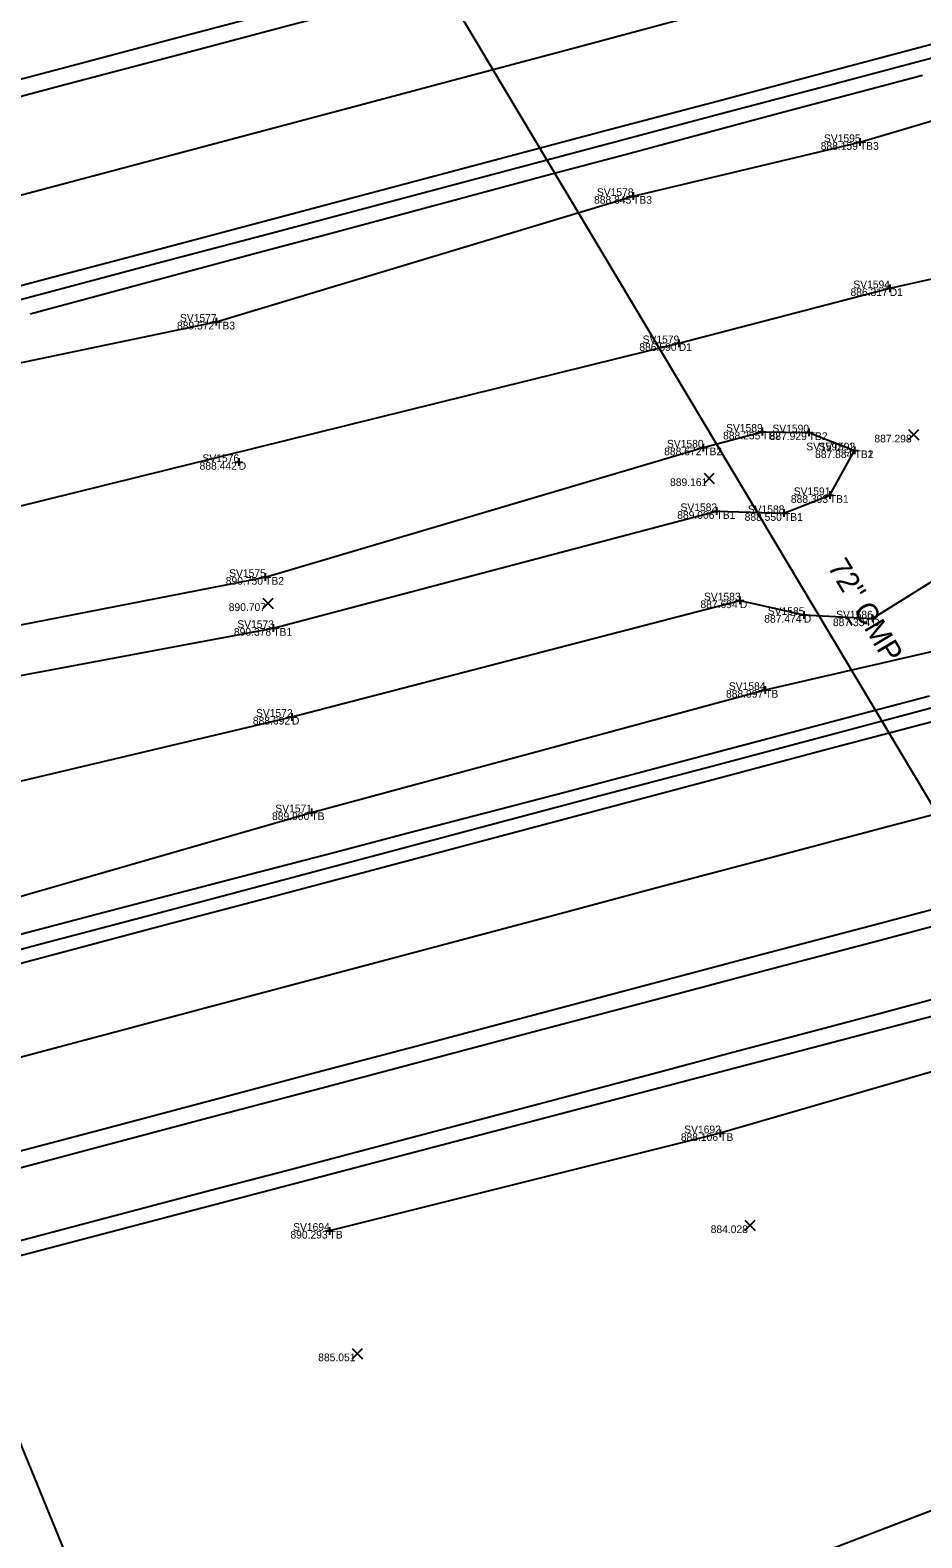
# Model space of a CAD drawing. Extents: x 2125299 to 2129212, y 713100 to 714300.
# Drawn here: x 2127549.2 to 2127665, y 713703.4 to 713899.3 of the extents above; entities that cross this region are included whole.
import ezdxf

# ---------------------------------------------------------------- set-up
doc = ezdxf.new("R2010")
doc.units = 0
for name, color, linetype in [('_CIVIL_CONSTRUCTION', 7, 'Continuous'), ('DR_X_Ditch', 7, 'Continuous'), ('DR_X_Storm_Sewer', 7, 'Continuous'), ('DR_X_Text', 7, 'Continuous'), ('DT_X_Terrain_Boundary', 7, 'Continuous'), ('PV_X_EOP', 7, 'Continuous'), ('PV_X_Shoulder_Rumble_Strip', 7, 'Continuous'), ('RW_P_Esmt_TMP', 7, 'Continuous'), ('RW_X_Esmt_CH', 7, 'Continuous'), ('RW_X_Fee_WL', 7, 'Continuous'), ('SC_Scratch1', 7, 'Continuous'), ('SC_Scratch2', 7, 'Continuous'), ('SV_X_Mon_Cells_Found', 7, 'Continuous'), ('SV_X_Text_Elevation', 7, 'Continuous'), ('SV_X_Toe_of_Slope', 7, 'Continuous'), ('SV_X_Top_of_Bank', 7, 'Continuous')]:
    doc.layers.add(name, color=color, linetype=linetype)

msp = doc.modelspace()

# ---------------------------------------------------------------- linework, layer by layer
at = {"layer": '_CIVIL_CONSTRUCTION'}
for points in [[(2127372.97, 713831.37), (2127387.47, 713835.22), (2127401.97, 713839.08), (2127416.46, 713842.93), (2127430.96, 713846.79), (2127445.46, 713850.64), (2127459.95, 713854.5), (2127474.45, 713858.35), (2127488.94, 713862.21), (2127503.44, 713866.06), (2127517.94, 713869.92), (2127532.43, 713873.77), (2127546.93, 713877.63), (2127561.42, 713881.48), (2127575.92, 713885.34), (2127590.42, 713889.19), (2127604.91, 713893.05), (2127619.41, 713896.9), (2127633.91, 713900.76), (2127648.4, 713904.61), (2127662.9, 713908.47), (2127677.41, 713912.28)], [(2127369.79, 713718.59), (2127384.29, 713722.43), (2127398.79, 713726.27), (2127413.29, 713730.11), (2127427.79, 713733.95), (2127442.29, 713737.79), (2127456.79, 713741.63), (2127471.29, 713745.47), (2127485.79, 713749.32), (2127500.28, 713753.18), (2127514.78, 713757.04), (2127529.27, 713760.9), (2127543.77, 713764.76), (2127558.26, 713768.62), (2127572.75, 713772.48), (2127587.25, 713776.34), (2127601.74, 713780.2), (2127616.24, 713784.07), (2127630.73, 713787.93), (2127645.23, 713791.77), (2127659.73, 713795.61), (2127674.23, 713799.44)]]:
    msp.add_lwpolyline(points, dxfattribs=at)
at = {"layer": 'DR_X_Ditch'}
for points in [[(2127104.46, 713722.2), (2127161.17, 713739.36), (2127224.94, 713755.07), (2127279.95, 713770.84), (2127341.71, 713787.57), (2127396.23, 713800.84), (2127459.54, 713814.71), (2127515.88, 713829.56), (2127633.42, 713858.63), (2127660.82, 713865.77), (2127680.17, 713870.09), (2127707.74, 713876.68), (2127734.62, 713883.6), (2127780.13, 713896.01), (2127811.25, 713900.24), (2127854.87, 713906.28), (2127890.1, 713912.55), (2127900.96, 713914.65)], [(2127114.72, 713683.53), (2127174.42, 713700.51), (2127233.48, 713715.29), (2127290.34, 713734.33), (2127349.42, 713751.95), (2127405.14, 713769), (2127465.12, 713782.63), (2127526.43, 713796.66), (2127583.18, 713810.08), (2127641.36, 713825.21), (2127649.66, 713823.32), (2127658.57, 713822.87), (2127670.43, 713830.25), (2127710.74, 713841.25), (2127737.15, 713847.1), (2127758.83, 713851.78)]]:
    msp.add_lwpolyline(points, dxfattribs=at)
at = {"layer": 'DR_X_Storm_Sewer'}
msp.add_line((2127551.46, 713991.15), (2127754.53, 713650.69), dxfattribs=at)
at = {"layer": 'DR_X_Text'}
msp.add_line((2127655.93, 713821.99), (2127655.44, 713822.83), dxfattribs=at)
at = {"layer": 'DT_X_Terrain_Boundary'}
msp.add_lwpolyline([(2127379.41, 713697.54), (2127389.08, 713700.09), (2127398.75, 713702.64), (2127408.42, 713705.18), (2127418.09, 713707.74), (2127427.76, 713710.3), (2127437.42, 713712.86), (2127447.09, 713715.42), (2127456.76, 713717.99), (2127466.42, 713720.55), (2127476.09, 713723.11), (2127485.74, 713725.66), (2127495.42, 713728.23), (2127505.09, 713730.78), (2127514.76, 713733.32), (2127524.43, 713735.87), (2127546.22, 713719.73), (2127560.16, 713685.63), (2127560.57, 713676.96), (2127582.81, 713665.2), (2127597.81, 713640.57), (2127738.64, 713599.23)], dxfattribs=at)
at = {"layer": 'PV_X_EOP'}
for points in [[(2127549.17, 713862.45), (2127558.82, 713865.04), (2127568.48, 713867.64), (2127578.14, 713870.23), (2127587.8, 713872.82), (2127597.46, 713875.41), (2127607.12, 713877.99), (2127616.78, 713880.58), (2127626.44, 713883.16), (2127636.1, 713885.74), (2127645.76, 713888.33), (2127655.42, 713890.89), (2127665.1, 713893.44)], [(2127540.23, 713779.85), (2127549.91, 713782.38), (2127559.59, 713784.9), (2127569.26, 713787.42), (2127578.94, 713789.95), (2127588.61, 713792.47), (2127598.29, 713794.99), (2127607.97, 713797.52), (2127617.64, 713800.04), (2127627.32, 713802.57), (2127636.98, 713805.13), (2127646.65, 713807.7), (2127656.31, 713810.27), (2127665.98, 713812.83)], [(2127543.78, 713740.96), (2127553.45, 713743.5), (2127563.12, 713746.05), (2127572.79, 713748.6), (2127582.46, 713751.14), (2127592.13, 713753.69), (2127601.8, 713756.23), (2127611.47, 713758.78), (2127621.14, 713761.34), (2127630.8, 713763.91), (2127640.46, 713766.49), (2127650.13, 713769.06), (2127659.79, 713771.64), (2127669.45, 713774.21)]]:
    msp.add_lwpolyline(points, dxfattribs=at)
at = {"layer": 'PV_X_Shoulder_Rumble_Strip'}
for points in [[(2127379.28, 713847.95), (2127393.77, 713851.83), (2127408.26, 713855.7), (2127422.75, 713859.58), (2127437.24, 713863.45), (2127451.73, 713867.33), (2127466.21, 713871.2), (2127480.7, 713875.08), (2127495.19, 713878.95), (2127509.68, 713882.82), (2127524.17, 713886.66), (2127538.67, 713890.5), (2127553.17, 713894.33), (2127567.67, 713898.17), (2127582.17, 713902), (2127596.67, 713905.84), (2127611.16, 713909.67), (2127625.66, 713913.5), (2127640.16, 713917.34), (2127654.66, 713921.17), (2127669.16, 713925.01)], [(2127378.03, 713819.22), (2127392.53, 713823.07), (2127407.02, 713826.92), (2127421.52, 713830.76), (2127436.02, 713834.61), (2127450.51, 713838.46), (2127465.01, 713842.3), (2127479.5, 713846.15), (2127494, 713849.99), (2127508.49, 713853.84), (2127522.99, 713857.69), (2127537.48, 713861.53), (2127551.98, 713865.38), (2127566.47, 713869.23), (2127580.97, 713873.07), (2127595.46, 713876.92), (2127609.96, 713880.76), (2127624.46, 713884.61), (2127638.95, 713888.46), (2127653.45, 713892.3), (2127667.94, 713896.15)], [(2127376.81, 713734.43), (2127391.3, 713738.29), (2127405.79, 713742.13), (2127420.29, 713745.98), (2127434.79, 713749.83), (2127449.28, 713753.68), (2127463.77, 713757.52), (2127478.27, 713761.37), (2127492.76, 713765.22), (2127507.26, 713769.07), (2127521.75, 713772.91), (2127536.25, 713776.76), (2127550.74, 713780.61), (2127565.24, 713784.46), (2127579.73, 713788.3), (2127594.23, 713792.15), (2127608.72, 713796), (2127623.22, 713799.85), (2127637.71, 713803.69), (2127652.21, 713807.54), (2127666.7, 713811.39)], [(2127369.47, 713704.27), (2127383.96, 713708.1), (2127398.46, 713711.94), (2127412.96, 713715.77), (2127427.46, 713719.61), (2127441.96, 713723.44), (2127456.45, 713727.28), (2127470.95, 713731.12), (2127485.45, 713734.96), (2127499.95, 713738.8), (2127514.44, 713742.64), (2127528.94, 713746.48), (2127543.43, 713750.32), (2127557.93, 713754.16), (2127572.43, 713758), (2127586.92, 713761.84), (2127601.42, 713765.68), (2127615.92, 713769.52), (2127630.41, 713773.36), (2127644.91, 713777.2), (2127659.41, 713781.04), (2127673.9, 713784.89)]]:
    msp.add_lwpolyline(points, dxfattribs=at)
at = {"layer": 'SC_Scratch1'}
msp.add_lwpolyline([(2127133.38, 713627.43), (2127166.26, 713637.18), (2127280.77, 713668.85), (2127395.3, 713699.47), (2127509.42, 713729.99), (2127750.89, 713793.4), (2127929.41, 713841.22)], dxfattribs=at)
at = {"layer": 'SC_Scratch2'}
for points in [[(2127379.92, 713845.89), (2127394.41, 713849.77), (2127408.9, 713853.64), (2127423.39, 713857.52), (2127437.89, 713861.39), (2127452.38, 713865.27), (2127466.87, 713869.14), (2127481.36, 713873.02), (2127495.85, 713876.89), (2127510.34, 713880.77), (2127524.84, 713884.61), (2127539.34, 713888.44), (2127553.84, 713892.28), (2127568.34, 713896.11), (2127582.85, 713899.95), (2127597.35, 713903.79), (2127611.85, 713907.62), (2127626.35, 713911.46), (2127640.85, 713915.29), (2127655.35, 713919.13), (2127669.85, 713922.96)], [(2127377.42, 713820.85), (2127391.91, 713824.7), (2127406.41, 713828.55), (2127420.91, 713832.4), (2127435.41, 713836.24), (2127449.91, 713840.09), (2127464.41, 713843.94), (2127478.9, 713847.78), (2127493.4, 713851.63), (2127507.9, 713855.48), (2127522.4, 713859.32), (2127536.9, 713863.17), (2127551.4, 713867.02), (2127565.89, 713870.86), (2127580.39, 713874.71), (2127594.89, 713878.56), (2127609.39, 713882.41), (2127623.89, 713886.25), (2127638.39, 713890.1), (2127652.88, 713893.95), (2127667.38, 713897.79)], [(2127377.56, 713732.82), (2127392.06, 713736.68), (2127406.56, 713740.53), (2127421.05, 713744.38), (2127435.55, 713748.23), (2127450.05, 713752.07), (2127464.55, 713755.92), (2127479.05, 713759.77), (2127493.54, 713763.62), (2127508.04, 713767.47), (2127522.54, 713771.32), (2127537.04, 713775.16), (2127551.54, 713779.01), (2127566.03, 713782.86), (2127580.53, 713786.71), (2127595.03, 713790.56), (2127609.53, 713794.41), (2127624.03, 713798.25), (2127638.52, 713802.1), (2127653.02, 713805.95), (2127667.52, 713809.8)], [(2127368.93, 713706.32), (2127383.43, 713710.16), (2127397.93, 713713.99), (2127412.43, 713717.83), (2127426.93, 713721.66), (2127441.43, 713725.5), (2127455.93, 713729.34), (2127470.43, 713733.18), (2127484.93, 713737.02), (2127499.43, 713740.86), (2127513.93, 713744.7), (2127528.43, 713748.54), (2127542.93, 713752.38), (2127557.43, 713756.22), (2127571.93, 713760.06), (2127586.43, 713763.9), (2127600.93, 713767.74), (2127615.43, 713771.58), (2127629.93, 713775.43), (2127644.43, 713779.27), (2127658.93, 713783.11), (2127673.43, 713786.96)]]:
    msp.add_lwpolyline(points, dxfattribs=at)
at = {"layer": 'SV_X_Mon_Cells_Found'}
for p, q in [((2127656.45, 713884.76), (2127657.45, 713884.76)), ((2127656.95, 713885.26), (2127656.95, 713884.26)), ((2127656.95, 713884.76), (2127656.95, 713884.76)), ((2127626.99, 713877.76), (2127627.99, 713877.76)), ((2127627.49, 713878.26), (2127627.49, 713877.26)), ((2127627.49, 713877.76), (2127627.49, 713877.76)), ((2127660.32, 713865.77), (2127661.32, 713865.77)), ((2127660.82, 713866.27), (2127660.82, 713865.27)), ((2127660.82, 713865.77), (2127660.82, 713865.77)), ((2127572.83, 713861.42), (2127573.83, 713861.42)), ((2127573.33, 713861.92), (2127573.33, 713860.92)), ((2127573.33, 713861.42), (2127573.33, 713861.42)), ((2127633.42, 713859.13), (2127633.42, 713858.13)), ((2127632.92, 713858.63), (2127633.92, 713858.63)), ((2127633.42, 713858.63), (2127633.42, 713858.63)), ((2127644.25, 713847.63), (2127644.25, 713846.63)), ((2127650.3, 713847.55), (2127650.3, 713846.55)), ((2127636.6, 713845.57), (2127636.6, 713844.57)), ((2127643.75, 713847.13), (2127644.75, 713847.13)), ((2127644.25, 713847.13), (2127644.25, 713847.13)), ((2127649.8, 713847.05), (2127650.8, 713847.05)), ((2127650.3, 713847.05), (2127650.3, 713847.05)), ((2127576.26, 713843.69), (2127576.26, 713842.69)), ((2127636.1, 713845.07), (2127637.1, 713845.07)), ((2127636.6, 713845.07), (2127636.6, 713845.07)), ((2127655.76, 713844.71), (2127656.76, 713844.71)), ((2127655.76, 713844.71), (2127656.76, 713844.71)), ((2127656.26, 713845.21), (2127656.26, 713844.21)), ((2127656.26, 713845.21), (2127656.26, 713844.21)), ((2127656.26, 713844.71), (2127656.26, 713844.71)), ((2127656.26, 713844.71), (2127656.26, 713844.71)), ((2127575.76, 713843.19), (2127576.76, 713843.19)), ((2127576.26, 713843.19), (2127576.26, 713843.19)), ((2127653.04, 713839.39), (2127653.04, 713838.39)), ((2127652.54, 713838.89), (2127653.54, 713838.89)), ((2127653.04, 713838.89), (2127653.04, 713838.89)), ((2127637.82, 713836.81), (2127638.82, 713836.81)), ((2127638.32, 713837.31), (2127638.32, 713836.31)), ((2127638.32, 713836.81), (2127638.32, 713836.81)), ((2127646.59, 713836.55), (2127647.59, 713836.55)), ((2127647.09, 713837.05), (2127647.09, 713836.05)), ((2127647.09, 713836.55), (2127647.09, 713836.55)), ((2127579.19, 713828.25), (2127580.19, 713828.25)), ((2127579.69, 713828.75), (2127579.69, 713827.75)), ((2127579.69, 713828.25), (2127579.69, 713828.25)), ((2127641.36, 713825.71), (2127641.36, 713824.71)), ((2127640.86, 713825.21), (2127641.86, 713825.21)), ((2127641.36, 713825.21), (2127641.36, 713825.21)), ((2127649.66, 713823.82), (2127649.66, 713822.82)), ((2127580.75, 713822.12), (2127580.75, 713821.12)), ((2127649.16, 713823.32), (2127650.16, 713823.32)), ((2127649.66, 713823.32), (2127649.66, 713823.32)), ((2127658.07, 713822.87), (2127659.07, 713822.87)), ((2127658.57, 713823.37), (2127658.57, 713822.37)), ((2127658.57, 713822.87), (2127658.57, 713822.87)), ((2127580.25, 713821.62), (2127581.25, 713821.62)), ((2127580.75, 713821.62), (2127580.75, 713821.62)), ((2127644.65, 713814.07), (2127644.65, 713813.07)), ((2127644.15, 713813.57), (2127645.15, 713813.57)), ((2127644.65, 713813.57), (2127644.65, 713813.57)), ((2127582.68, 713810.08), (2127583.68, 713810.08)), ((2127583.18, 713810.58), (2127583.18, 713809.58)), ((2127583.18, 713810.08), (2127583.18, 713810.08)), ((2127585.2, 713797.67), (2127586.2, 713797.67)), ((2127585.7, 713798.17), (2127585.7, 713797.17)), ((2127585.7, 713797.67), (2127585.7, 713797.67)), ((2127638.3, 713755.97), (2127639.3, 713755.97)), ((2127638.8, 713756.47), (2127638.8, 713755.47)), ((2127638.8, 713755.97), (2127638.8, 713755.97)), ((2127588.05, 713743.79), (2127588.05, 713742.79)), ((2127587.55, 713743.29), (2127588.55, 713743.29)), ((2127588.05, 713743.29), (2127588.05, 713743.29))]:
    msp.add_line(p, q, dxfattribs=at)
at = {"layer": 'SV_X_Text_Elevation'}
for p, q in [((2127663.28, 713846.08), (2127664.61, 713847.41)), ((2127663.28, 713847.41), (2127664.61, 713846.08)), ((2127636.71, 713840.4), (2127638.04, 713841.74)), ((2127636.71, 713841.74), (2127638.04, 713840.4)), ((2127579.4, 713824.17), (2127580.73, 713825.51)), ((2127579.4, 713825.51), (2127580.73, 713824.17)), ((2127642.01, 713743.33), (2127643.34, 713744.66)), ((2127642.01, 713744.66), (2127643.34, 713743.33)), ((2127591.01, 713726.68), (2127592.34, 713728.02)), ((2127591.01, 713728.02), (2127592.34, 713726.68))]:
    msp.add_line(p, q, dxfattribs=at)
at = {"layer": 'SV_X_Toe_of_Slope'}
msp.add_lwpolyline([(2127560.57, 713676.96), (2127620.08, 713691.3), (2127651.95, 713701.51), (2127685.52, 713714.38), (2127712.77, 713721.61), (2127733.87, 713722.46), (2127761.63, 713729.12), (2127790.85, 713736.75), (2127822.01, 713745.03), (2127854.59, 713754.33)], dxfattribs=at)
at = {"layer": 'SV_X_Top_of_Bank'}
for points in [[(2127101.4, 713732.92), (2127157.86, 713749.53), (2127222.47, 713767.6), (2127276.61, 713783.01), (2127338.05, 713802.99), (2127391.69, 713816.17), (2127455.85, 713833.15), (2127455.8, 713833.25), (2127510.11, 713848.18), (2127573.33, 713861.42), (2127627.49, 713877.76), (2127656.95, 713884.76), (2127703.68, 713898.62), (2127726.61, 713904.03), (2127772.75, 713915.63), (2127805.28, 713925.94), (2127847.55, 713937.37), (2127886.63, 713945.55), (2127933.44, 713957.72), (2127971.8, 713964.93)], [(2127118.3, 713671.13), (2127177.41, 713689.33), (2127235.14, 713704.98), (2127293.81, 713721.23), (2127351.9, 713736.5), (2127410.59, 713750.81), (2127468.4, 713765.95), (2127530.81, 713781.83), (2127585.7, 713797.67), (2127644.65, 713813.57), (2127714.44, 713829.64), (2127739.44, 713835.61), (2127786.69, 713848.08), (2127820.06, 713857.41), (2127851.23, 713864.33), (2127885.98, 713873.89), (2127912.04, 713881.53)], [(2127107.63, 713707.93), (2127165.88, 713728.25), (2127226.9, 713744.76), (2127282.29, 713761.25), (2127344.58, 713774.07), (2127399.24, 713790.19), (2127462.5, 713800.9), (2127519.74, 713816.54), (2127579.69, 713828.25), (2127636.6, 713845.07), (2127644.25, 713847.13), (2127650.3, 713847.05), (2127656.26, 713844.71)], [(2127109.56, 713700.01), (2127169.1, 713718.64), (2127229.09, 713734.94), (2127284.98, 713752.73), (2127346.09, 713765.57), (2127402.41, 713780.38), (2127463.19, 713795.69), (2127522.45, 713810.68), (2127580.75, 713821.62), (2127638.32, 713836.81), (2127647.09, 713836.55), (2127653.04, 713838.89), (2127656.26, 713844.71)], [(2127920.85, 713834.18), (2127873.9, 713818.39), (2127828.31, 713807.04), (2127782.81, 713794.43), (2127731.94, 713780.7), (2127685.41, 713769.5), (2127638.8, 713755.97), (2127588.05, 713743.29)]]:
    msp.add_lwpolyline(points, dxfattribs=at)

# ---------------------------------------------------------------- texts
at = {"layer": 'DR_X_Text'}
msp.add_text('72" CMP', height=2.8, rotation=300.8145, dxfattribs=at).set_placement((2127652.68, 713829.6))
at = {"layer": 'RW_P_Esmt_TMP'}
for s, p in [('TB3', (2127656.95, 713883.76)), ('TB3', (2127627.49, 713876.76)), ('D1', (2127660.82, 713864.77)), ('TB3', (2127573.33, 713860.42)), ('D1', (2127633.42, 713857.63)), ('TB2', (2127644.25, 713846.13)), ('TB2', (2127650.3, 713846.05)), ('TB2', (2127636.6, 713844.07)), ('TB2', (2127656.26, 713843.71)), ('TB1', (2127656.26, 713843.71)), ('D', (2127576.26, 713842.19)), ('TB1', (2127653.04, 713837.89)), ('TB1', (2127638.32, 713835.81)), ('TB1', (2127647.09, 713835.55)), ('TB2', (2127579.69, 713827.25)), ('D', (2127641.36, 713824.21)), ('D', (2127649.66, 713822.32)), ('D', (2127658.57, 713821.87)), ('TB1', (2127580.75, 713820.62)), ('TB', (2127644.65, 713812.57)), ('D', (2127583.18, 713809.08)), ('TB', (2127585.7, 713796.67)), ('TB', (2127638.8, 713754.97)), ('TB', (2127588.05, 713742.29))]:
    msp.add_text(s, height=1, dxfattribs=at).set_placement(p)
at = {"layer": 'RW_X_Esmt_CH'}
for s, p in [('SV1595', (2127652.28, 713884.76)), ('SV1578', (2127622.79, 713877.76)), ('SV1594', (2127656.1, 713865.77)), ('SV1577', (2127568.63, 713861.42)), ('SV1579', (2127628.73, 713858.63)), ('SV1589', (2127639.57, 713847.13)), ('SV1590', (2127645.59, 713847.05)), ('SV1580', (2127631.89, 713845.07)), ('SV1592_1', (2127649.99, 713844.71)), ('SV1592', (2127651.58, 713844.71)), ('SV1576', (2127571.56, 713843.19)), ('SV1591', (2127648.36, 713838.89)), ('SV1582', (2127633.65, 713836.81)), ('SV1588', (2127642.39, 713836.55)), ('SV1575', (2127575.02, 713828.25)), ('SV1583', (2127636.7, 713825.21)), ('SV1585', (2127644.99, 713823.32)), ('SV1586', (2127653.87, 713822.87)), ('SV1573', (2127576.08, 713821.62)), ('SV1584', (2127639.93, 713813.57)), ('SV1572', (2127578.51, 713810.08)), ('SV1571', (2127581.02, 713797.67)), ('SV1692', (2127634.13, 713755.97)), ('SV1694', (2127583.33, 713743.29))]:
    msp.add_text(s, height=1, dxfattribs=at).set_placement(p)
at = {"layer": 'RW_X_Fee_WL'}
for s, p in [('888.159', (2127651.86, 713883.76)), ('888.845', (2127622.42, 713876.76)), ('886.317', (2127655.73, 713864.77)), ('889.572', (2127568.25, 713860.42)), ('886.590', (2127628.3, 713857.63)), ('888.255', (2127639.18, 713846.13)), ('887.929', (2127645.22, 713846.05)), ('887.298', (2127658.84, 713845.74)), ('888.672', (2127631.53, 713844.07)), ('887.884', (2127651.13, 713843.71)), ('887.884', (2127651.13, 713843.71)), ('888.442', (2127571.18, 713842.19)), ('889.161', (2127632.29, 713840.07)), ('888.393', (2127647.98, 713837.89)), ('889.006', (2127633.22, 713835.81)), ('888.550', (2127641.98, 713835.55)), ('890.750', (2127574.58, 713827.25)), ('890.707', (2127574.97, 713823.84)), ('887.694', (2127636.24, 713824.21)), ('887.474', (2127644.53, 713822.32)), ('887.334', (2127653.45, 713821.87)), ('890.378', (2127575.64, 713820.62)), ('888.997', (2127639.56, 713812.57)), ('888.692', (2127578.1, 713809.08)), ('889.900', (2127580.59, 713796.67)), ('888.106', (2127633.69, 713754.97)), ('884.028', (2127637.57, 713743)), ('890.293', (2127582.98, 713742.29)), ('885.051', (2127586.59, 713726.35))]:
    msp.add_text(s, height=1, dxfattribs=at).set_placement(p)

doc.saveas('drawing.dxf')
